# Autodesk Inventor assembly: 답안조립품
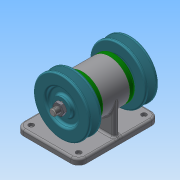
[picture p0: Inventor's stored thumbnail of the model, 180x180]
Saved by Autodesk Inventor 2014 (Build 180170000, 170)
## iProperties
Created: 2019-09
Part Number: 답안조립품
Document SubType Name: Assembly
Designer: net
Author: net
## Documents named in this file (10)
- C:\Users\net\Desktop\490904v1042\답안조립품.iam
- C:\Users\net\Desktop\490904v1042\본체.ipt
- C:\Users\net\Desktop\490904v1042\V-벨트풀리.ipt
- C:\Users\net\Desktop\490904v1042\너트 M10x1.ipt
- C:\Users\net\Desktop\490904v1042\베어링 6004.ipt
- C:\Users\net\Desktop\490904v1042\볼트 M4.ipt
- C:\Users\net\Desktop\490904v1042\오일 실 17 30 5.ipt
- C:\Users\net\Desktop\490904v1042\축.ipt
- C:\Users\net\Desktop\490904v1042\커버.ipt
- C:\Users\net\Desktop\490904v1042\키 5 x 5 x 12.ipt
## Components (2 placed, 1 different names)
1. V-벨트풀리:1 — 각도:4
2. V-벨트풀리:2 — 각도:3
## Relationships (2: Angle 2)
- 각도:3 [Angle]: V-벨트풀리:2
- 각도:4 [Angle]: V-벨트풀리:1
